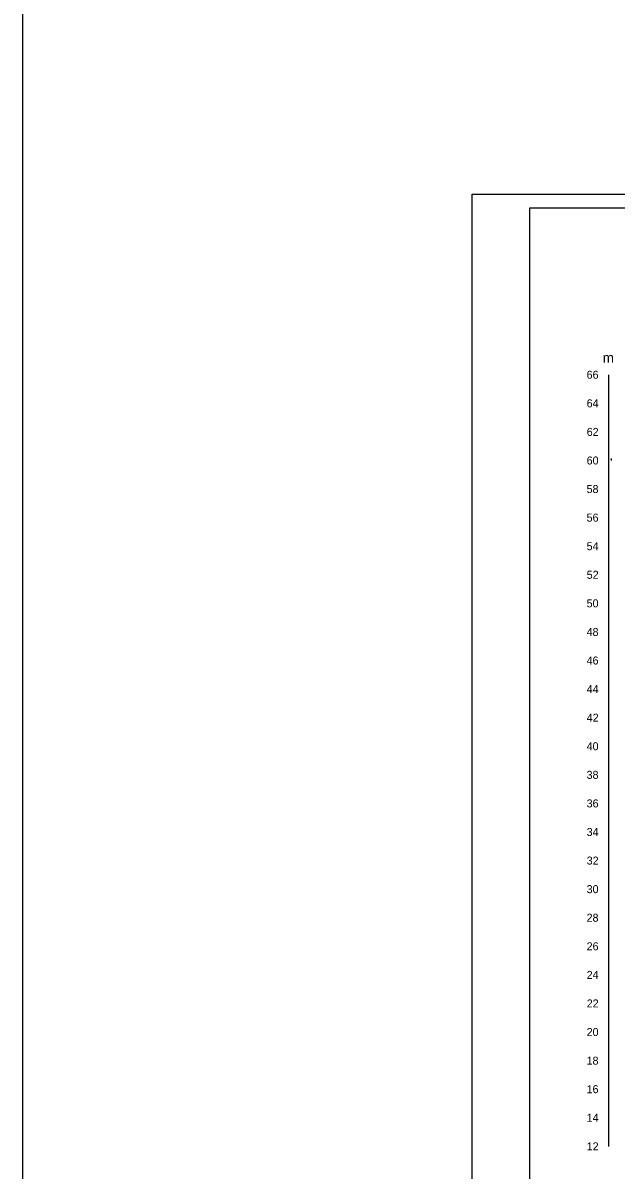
# Model space of a CAD drawing. Extents: x 700746 to 706058, y 6570320 to 6580460.
# Drawn here: x 703703 to 704118, y 6574687 to 6575490 of the extents above; entities that cross this region are included whole.
import ezdxf

# ---------------------------------------------------------------- set-up
doc = ezdxf.new("R2010")
doc.units = 0
for name, color, linetype in [('ABIJOONIS', 7, 'Continuous'), ('Kaitsevöönd', 7, 'Continuous'), ('VEEKOGU', 7, 'Continuous'), ('Veetase', 7, 'Continuous'), ('VORMISTUS', 7, 'Continuous')]:
    doc.layers.add(name, color=color, linetype=linetype)

msp = doc.modelspace()

# ---------------------------------------------------------------- linework, layer by layer
at = {"layer": 'ABIJOONIS'}
msp.add_lwpolyline([(704017.06, 6575370.2), (705897.06, 6575370.2), (705897.06, 6574500.2), (704017.06, 6574500.2), (704017.06, 6575370.2)], dxfattribs=at)
at = {"layer": 'Kaitsevöönd'}
msp.add_lwpolyline([(705910.76, 6574141.69), (703702.63, 6574141.69), (703702.63, 6577055.71), (705007.71, 6577055.71)], dxfattribs=at)
at = {"layer": 'VEEKOGU'}
msp.add_line((704114.42, 6575183.73), (704114.42, 6575185.03), dxfattribs=at)
at = {"layer": 'Veetase'}
msp.add_line((704114.42, 6575183.73), (704114.42, 6575185.03), dxfattribs=at)
at = {"layer": 'VORMISTUS'}
msp.add_line((704112.42, 6575243.73), (704112.42, 6574703.73), dxfattribs=at)
msp.add_lwpolyline([(704057.06, 6574510.2), (705887.06, 6574510.2), (705887.06, 6575360.2), (704057.06, 6575360.2)], close=True, dxfattribs=at)

# ---------------------------------------------------------------- texts
for s, height, p in [('m', 7, (704108.35, 6575252.2)), ('66', 5.6, (704097.07, 6575240.93)), ('64', 5.6, (704097.1, 6575220.93)), ('62', 5.6, (704097.13, 6575200.93)), ('60', 5.6, (704097.09, 6575180.93)), ('58', 5.6, (704097.06, 6575160.93)), ('56', 5.6, (704097.07, 6575140.93)), ('54', 5.6, (704097.1, 6575120.93)), ('52', 5.6, (704097.13, 6575100.93)), ('50', 5.6, (704097.09, 6575080.93)), ('48', 5.6, (704097.06, 6575060.93)), ('46', 5.6, (704097.07, 6575040.93)), ('44', 5.6, (704097.1, 6575020.93)), ('42', 5.6, (704097.13, 6575000.93)), ('40', 5.6, (704097.09, 6574980.93)), ('38', 5.6, (704097.06, 6574960.93)), ('36', 5.6, (704097.07, 6574940.93)), ('34', 5.6, (704097.1, 6574920.93)), ('32', 5.6, (704097.13, 6574900.93)), ('30', 5.6, (704097.09, 6574880.93)), ('28', 5.6, (704097.06, 6574860.93)), ('26', 5.6, (704097.07, 6574840.93)), ('24', 5.6, (704097.1, 6574820.93)), ('22', 5.6, (704097.13, 6574800.93)), ('20', 5.6, (704097.09, 6574780.93)), ('18', 5.6, (704097.06, 6574760.93)), ('16', 5.6, (704097.07, 6574740.93)), ('14', 5.6, (704097.1, 6574720.93)), ('12', 5.6, (704097.13, 6574700.93))]:
    msp.add_text(s, height=height, dxfattribs=at).set_placement(p)

doc.saveas('drawing.dxf')
